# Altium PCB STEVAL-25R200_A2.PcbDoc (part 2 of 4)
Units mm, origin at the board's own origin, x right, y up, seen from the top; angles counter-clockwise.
Board outline 84.5 x 100 mm, 4 copper layers (Top Layer, F2, F3, Bottom Layer), stack 0.78 mm thick; 272 components, 152 nets, 679 pads, 380 vias.
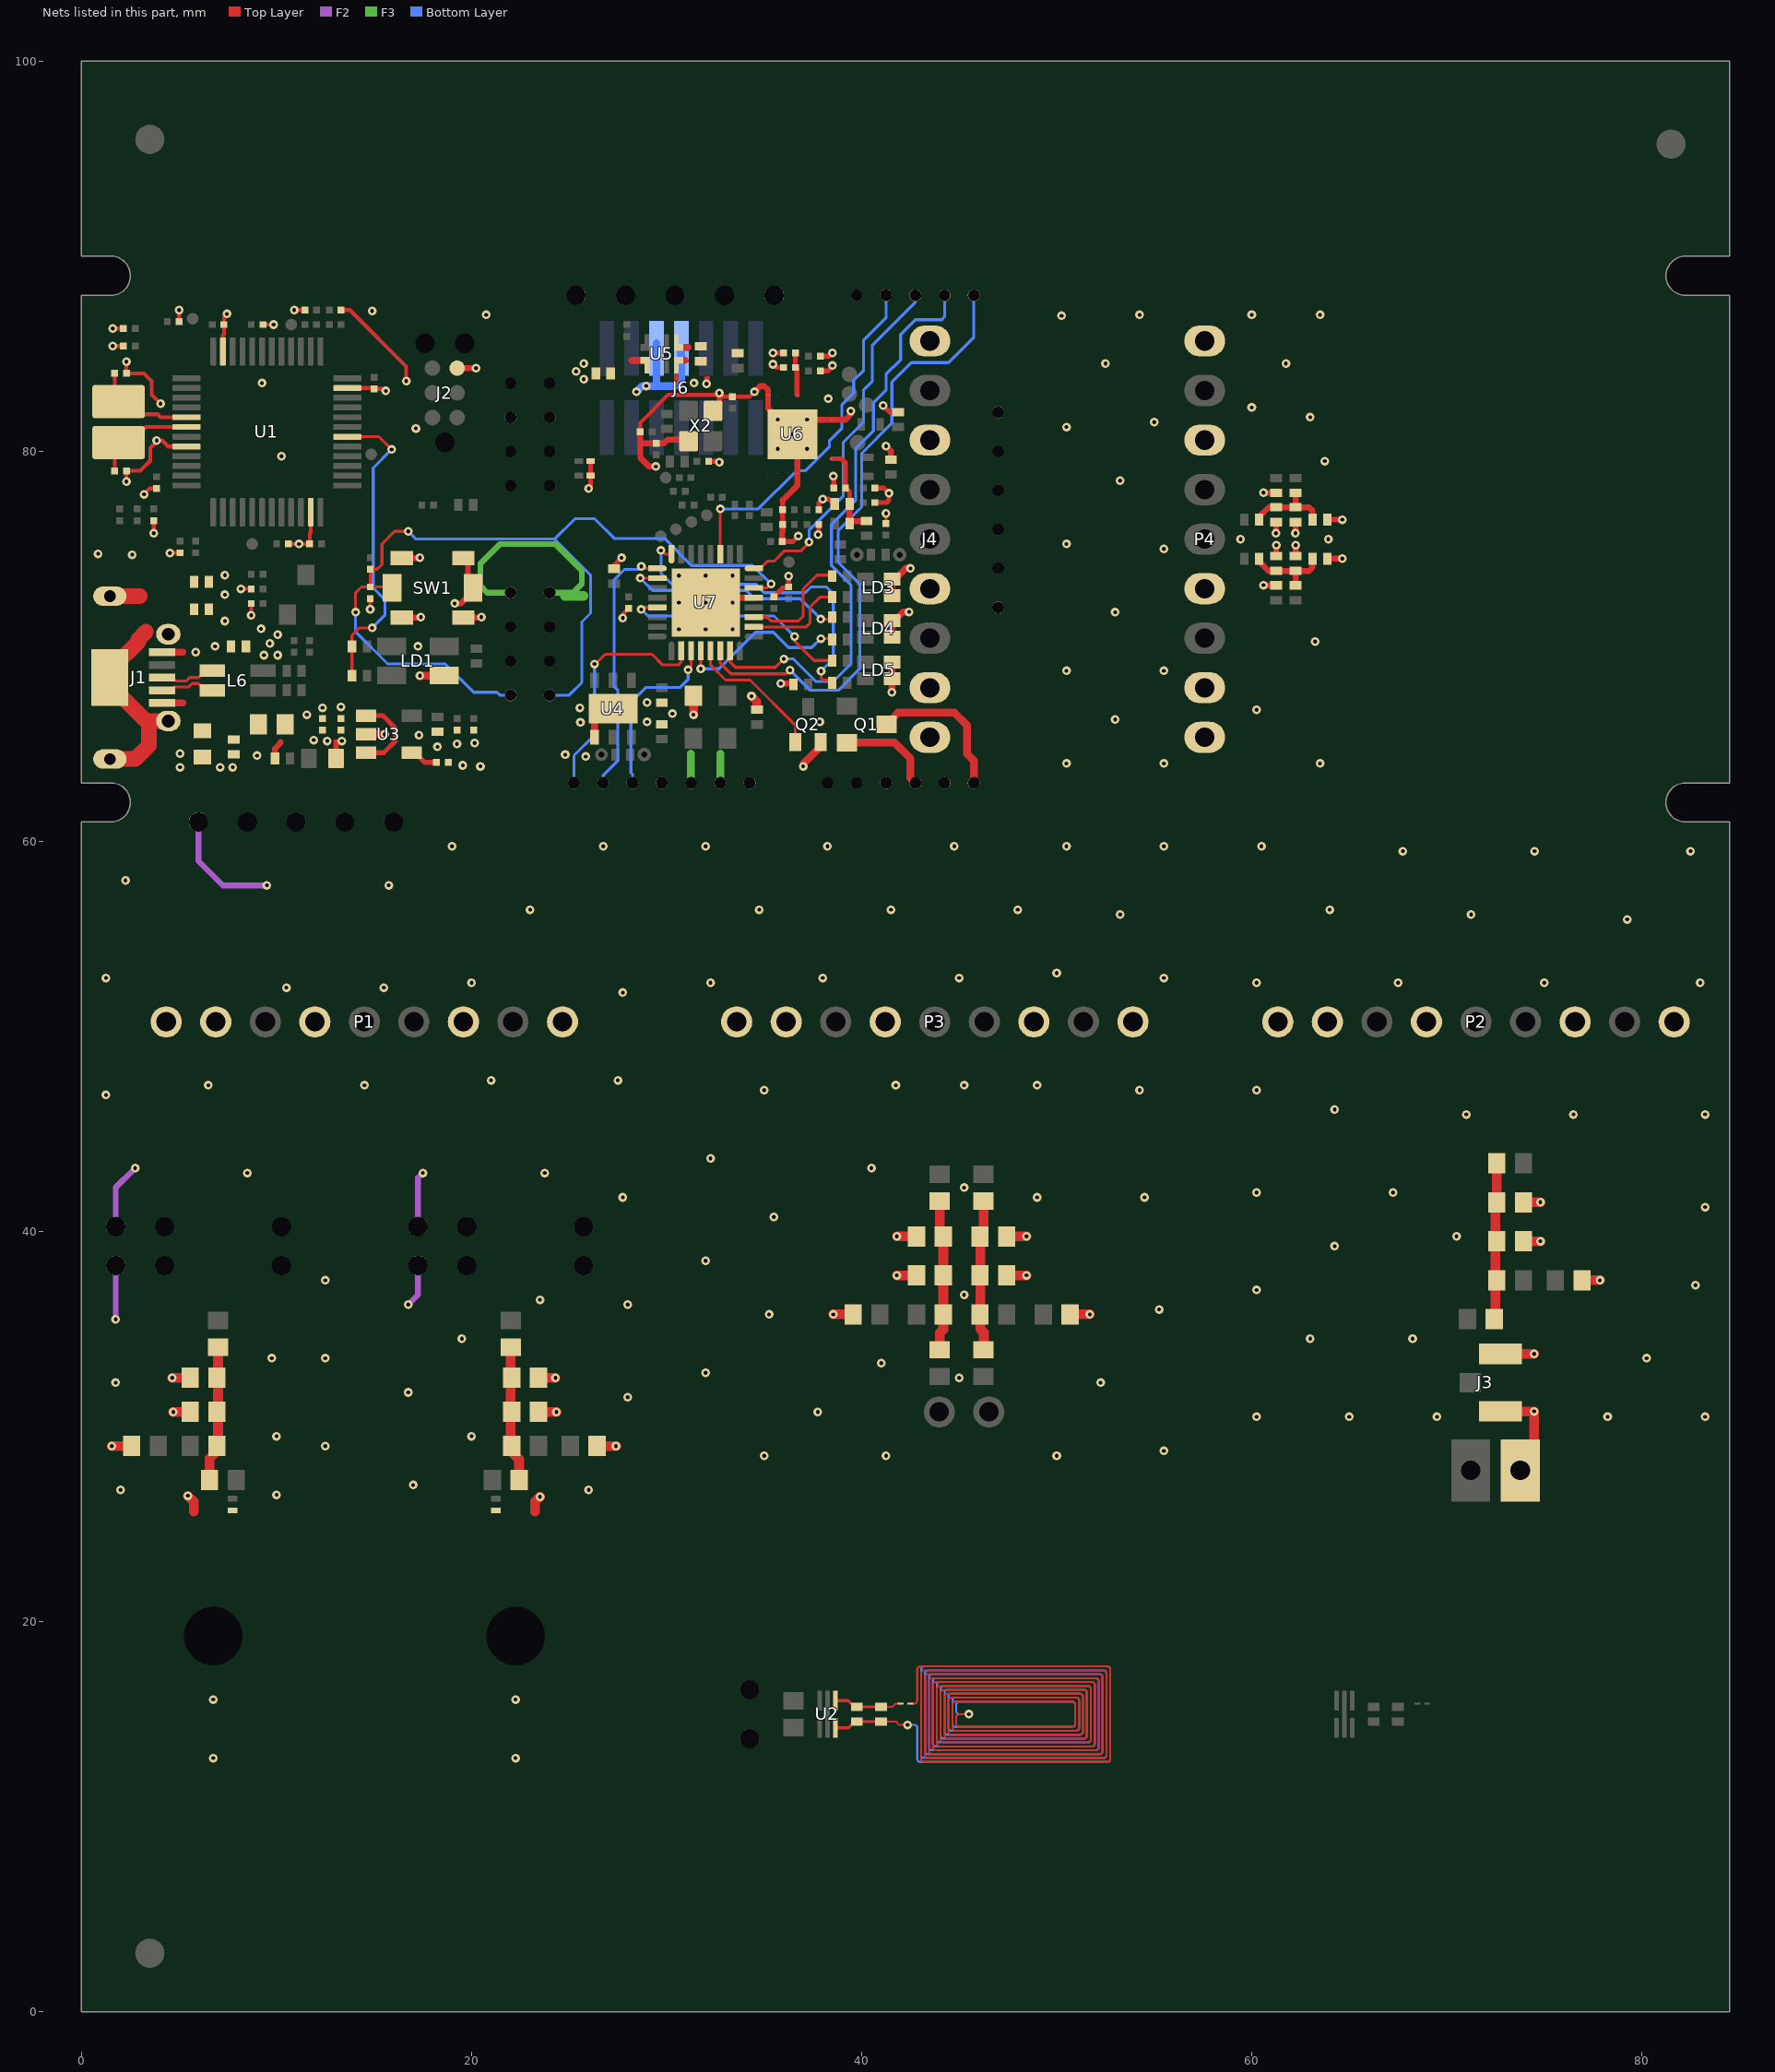
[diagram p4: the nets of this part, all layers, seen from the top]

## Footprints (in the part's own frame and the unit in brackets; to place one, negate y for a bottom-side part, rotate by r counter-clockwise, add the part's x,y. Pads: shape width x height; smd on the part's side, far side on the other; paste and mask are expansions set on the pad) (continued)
ST-QFN24-PAS0.5-4X4-THPAD-2.8MAX [mil]
  round 1 smd: 1(-79.25,49.21) 2(-79.25,29.53) 3(-79.25,9.84) 4(-79.25,-9.84) 5(-79.25,-29.53) 6(-79.25,-49.21) 7(-49.21,-79.25) 8(-29.53,-79.25) 9(-9.84,-79.25) 10(9.84,-79.25) 11(29.53,-79.25) 12(49.21,-79.25) 13(79.25,-49.21) 14(79.25,-29.53) 15(79.25,-9.84) 16(79.25,9.84) 17(79.25,29.53) 18(79.25,49.21) 19(49.21,79.25) 20(29.53,79.25) 21(9.84,79.25) 22(-9.84,79.25) 23(-29.53,79.25) 24(-49.21,79.25)
  rect 100.39x100.39 smd paste-118.11 mask-118.11: 25(0,0)
  Top Layer region: -68.92,43.31 -95.49,43.31 -95.49,55.12 -68.92,55.12 -66.66,54.67 -64.74,53.39 -63.46,51.47 -63.01,49.21 -63.01,49.21 -63.46,46.95 -64.74,45.04 -66.66,43.76 -68.92,43.31
  Top Layer region: -68.92,23.62 -95.49,23.62 -95.49,35.43 -68.92,35.43 -66.66,34.98 -64.74,33.7 -63.46,31.79 -63.01,29.53 -63.01,29.53 -63.46,27.27 -64.74,25.35 -66.66,24.07 -68.92,23.62
  Top Layer region: -68.92,3.94 -95.49,3.94 -95.49,15.75 -68.92,15.75 -66.66,15.3 -64.74,14.02 -63.46,12.1 -63.01,9.84 -63.01,9.84 -63.46,7.58 -64.74,5.67 -66.66,4.39 -68.92,3.94
  Top Layer region: -68.92,-15.75 -95.49,-15.75 -95.49,-3.94 -68.92,-3.94 -66.66,-4.39 -64.74,-5.67 -63.46,-7.58 -63.01,-9.84 -63.01,-9.84 -63.46,-12.1 -64.74,-14.02 -66.66,-15.3 -68.92,-15.75
  Top Layer region: -68.92,-35.43 -95.49,-35.43 -95.49,-23.62 -68.92,-23.62 -66.66,-24.07 -64.74,-25.35 -63.46,-27.27 -63.01,-29.53 -63.01,-29.53 -63.46,-31.79 -64.74,-33.7 -66.66,-34.98 -68.92,-35.43
  Top Layer region: -68.92,-55.12 -95.49,-55.12 -95.49,-43.31 -68.92,-43.31 -66.66,-43.76 -64.74,-45.04 -63.46,-46.95 -63.01,-49.21 -63.01,-49.21 -63.46,-51.47 -64.74,-53.39 -66.66,-54.67 -68.92,-55.12
  Top Layer region: -43.31,-68.92 -43.31,-95.49 -55.12,-95.49 -55.12,-68.92 -54.67,-66.66 -53.39,-64.74 -51.47,-63.46 -49.21,-63.01 -49.21,-63.01 -46.95,-63.46 -45.04,-64.74 -43.76,-66.66 -43.31,-68.92
  Top Layer region: -23.62,-68.92 -23.62,-95.49 -35.43,-95.49 -35.43,-68.92 -34.98,-66.66 -33.7,-64.74 -31.79,-63.46 -29.53,-63.01 -29.53,-63.01 -27.27,-63.46 -25.35,-64.74 -24.07,-66.66 -23.62,-68.92
  Top Layer region: -3.94,-68.92 -3.94,-95.49 -15.75,-95.49 -15.75,-68.92 -15.3,-66.66 -14.02,-64.74 -12.1,-63.46 -9.84,-63.01 -9.84,-63.01 -7.58,-63.46 -5.67,-64.74 -4.39,-66.66 -3.94,-68.92
  Top Layer region: 15.75,-68.92 15.75,-95.49 3.94,-95.49 3.94,-68.92 4.39,-66.66 5.67,-64.74 7.58,-63.46 9.84,-63.01 9.84,-63.01 12.1,-63.46 14.02,-64.74 15.3,-66.66 15.75,-68.92
  Top Layer region: 35.43,-68.92 35.43,-95.49 23.62,-95.49 23.62,-68.92 24.07,-66.66 25.35,-64.74 27.27,-63.46 29.53,-63.01 29.53,-63.01 31.79,-63.46 33.7,-64.74 34.98,-66.66 35.43,-68.92
  Top Layer region: 55.12,-68.92 55.12,-95.49 43.31,-95.49 43.31,-68.92 43.76,-66.66 45.04,-64.74 46.95,-63.46 49.21,-63.01 49.21,-63.01 51.47,-63.46 53.39,-64.74 54.67,-66.66 55.12,-68.92
  Top Layer region: 68.92,-43.31 95.49,-43.31 95.49,-55.12 68.92,-55.12 66.66,-54.67 64.74,-53.39 63.46,-51.47 63.01,-49.21 63.01,-49.21 63.46,-46.95 64.74,-45.04 66.66,-43.76 68.92,-43.31
  Top Layer region: 68.92,-23.62 95.49,-23.62 95.49,-35.43 68.92,-35.43 66.66,-34.98 64.74,-33.7 63.46,-31.79 63.01,-29.53 63.01,-29.53 63.46,-27.27 64.74,-25.35 66.66,-24.07 68.92,-23.62
  Top Layer region: 68.92,-3.94 95.49,-3.94 95.49,-15.75 68.92,-15.75 66.66,-15.3 64.74,-14.02 63.46,-12.1 63.01,-9.84 63.01,-9.84 63.46,-7.58 64.74,-5.67 66.66,-4.39 68.92,-3.94
  Top Layer region: 68.92,15.75 95.49,15.75 95.49,3.94 68.92,3.94 66.66,4.39 64.74,5.67 63.46,7.58 63.01,9.84 63.01,9.84 63.46,12.1 64.74,14.02 66.66,15.3 68.92,15.75
  Top Layer region: 68.92,35.43 95.49,35.43 95.49,23.62 68.92,23.62 66.66,24.07 64.74,25.35 63.46,27.27 63.01,29.53 63.01,29.53 63.46,31.79 64.74,33.7 66.66,34.98 68.92,35.43
  Top Layer region: 68.92,55.12 95.49,55.12 95.49,43.31 68.92,43.31 66.66,43.76 64.74,45.04 63.46,46.95 63.01,49.21 63.01,49.21 63.46,51.47 64.74,53.39 66.66,54.67 68.92,55.12
  Top Layer region: 43.31,68.92 43.31,95.49 55.12,95.49 55.12,68.92 54.67,66.66 53.39,64.74 51.47,63.46 49.21,63.01 49.21,63.01 46.95,63.46 45.04,64.74 43.76,66.66 43.31,68.92
  Top Layer region: 23.62,68.92 23.62,95.49 35.43,95.49 35.43,68.92 34.98,66.66 33.7,64.74 31.79,63.46 29.53,63.01 29.53,63.01 27.27,63.46 25.35,64.74 24.07,66.66 23.62,68.92
  Top Layer region: 3.94,68.92 3.94,95.49 15.75,95.49 15.75,68.92 15.3,66.66 14.02,64.74 12.1,63.46 9.84,63.01 9.84,63.01 7.58,63.46 5.67,64.74 4.39,66.66 3.94,68.92
  Top Layer region: -15.75,68.92 -15.75,95.49 -3.94,95.49 -3.94,68.92 -4.39,66.66 -5.67,64.74 -7.58,63.46 -9.84,63.01 -9.84,63.01 -12.1,63.46 -14.02,64.74 -15.3,66.66 -15.75,68.92
  Top Layer region: -35.43,68.92 -35.43,95.49 -23.62,95.49 -23.62,68.92 -24.07,66.66 -25.35,64.74 -27.27,63.46 -29.53,63.01 -29.53,63.01 -31.79,63.46 -33.7,64.74 -34.98,66.66 -35.43,68.92
  Top Layer region: -55.12,68.92 -55.12,95.49 -43.31,95.49 -43.31,68.92 -43.76,66.66 -45.04,64.74 -46.95,63.46 -49.21,63.01 -49.21,63.01 -51.47,63.46 -53.39,64.74 -54.67,66.66 -55.12,68.92
  silkscreen extent -110,-83 83,83, body extent -83,-83 83,83, height 40
ST-ROHS-CHINOIS-10ans [mm]
  silkscreen extent -3,-2.51 2.99,2.68
ST-ROHS-optimised [mm]
  silkscreen extent -2.76,-1.63 2.72,1.95
ST-ST0201 [mm]
  rect 0.3x0.44 smd: A(0,-0.3) K(0,0.3)
  silkscreen extent -0.57,0.33 -0.43,0.47, body extent -0.18,-0.33 0.18,0.33, height 0.33
ST-UFDFPN5-Pas=0.4-PKG-1.7x1.4 [mm]
  rect 0.25x1 smd: 1(0.4,0.7) 3(-0.4,0.7) 4(-0.4,-0.7) 5(0.4,-0.7)
  rect 0.25x2.4 smd: 2(0,0)
  Top Layer keep-out region: 0.55,0.175 0.15,0.175 0.15,-0.175 0.55,-0.175
  Top Layer keep-out region: -0.55,-0.175 -0.15,-0.175 -0.15,0.175 -0.55,0.175
  silkscreen extent -0.8,-0.75 0.8,1.83, body extent -0.75,-0.9 0.75,0.9, height 0.6
ST-UFQFPN32-PAS-0.5-PKG-5X5X0.55 [mm]
  rect 0.3x0.3 smd: 1(-2.8,1.75) 8(-2.8,-1.75) 9(-1.75,-2.8) 16(1.75,-2.8) 17(2.8,-1.75) 24(2.8,1.75) 25(1.75,2.8) 32(-1.75,2.8)
  oval 0.95x0.3 smd: 1(-2.475,1.75) 8(-2.475,-1.75) 17(2.475,-1.75) 24(2.475,1.75)
  rect 0.95x0.3 smd: 2(-2.475,1.25) 3(-2.475,0.75) 4(-2.475,0.25) 5(-2.475,-0.25) 6(-2.475,-0.75) 7(-2.475,-1.25) 18(2.475,-1.25) 19(2.475,-0.75) 20(2.475,-0.25) 21(2.475,0.25) 22(2.475,0.75) 23(2.475,1.25)
  oval 0.3x0.95 smd: 9(-1.75,-2.475) 16(1.75,-2.475) 25(1.75,2.475) 32(-1.75,2.475)
  rect 0.3x0.95 smd: 10(-1.25,-2.475) 11(-0.75,-2.475) 12(-0.25,-2.475) 13(0.25,-2.475) 14(0.75,-2.475) 15(1.25,-2.475) 26(1.25,2.475) 27(0.75,2.475) 28(0.25,2.475) 29(-0.25,2.475) 30(-0.75,2.475) 31(-1.25,2.475)
  rect 3.5x3.5 smd paste-0.35 mask-0.1: 33(0,0)
  silkscreen extent -3.22,-2.6 2.6,2.72, body extent -2.6,-2.6 2.6,2.6, height 0.61
STRAP-FORMAT-0402-OUVERT [mil]
  rect 24x17 smd paste-39.37: 1(0,-15) 2(0,15)
  Top Layer region: -11.81,20.87 -11.81,1.92 0.05,6.71 11.81,1.96 11.81,20.87
  Top Layer region: -11.81,-22.44 -11.81,-6.97 0,-1.97 11.81,-6.97 11.81,-22.44
  silkscreen extent -22,-2 -22,12, body extent -12,-24 12,24, height 1
STRAP-FORMAT-0603-OUVERT [mil]
  rect 41x35 smd paste-35.43: 1(0,-27) 2(0,27)
  Top Layer region: -20.47,37.4 -20.47,-0.79 0.05,7.5 20.47,-0.75 20.47,37.4
  Top Layer region: -20.47,-38.19 -20.47,-9.84 0,-1.18 20.47,-9.84 20.47,-38.19
  silkscreen extent -31,-37 31,38
TAG-CONNECT-FOOTPRINT-TC2030-IDC-NL [mm]
  round 0.8 smd paste-1: 1(-1.27,-0.635) 2(-1.27,0.635) 3(0,-0.635) 4(0,0.635) 5(1.27,-0.635) 6(1.27,0.635)
  round 0.5 hole 1 unplated: MEC(-2.54,0) MEC(2.54,-1.016) MEC(2.54,1.016)
  Top Layer keep-out region: 0.445,0.635 0.826,0.635 0.826,0.624 0.859,0.458 0.953,0.318 0.953,0.318 1.093,0.224 1.259,0.191 1.259,0.191 1.27,0.191 1.27,-0.19 1.259,-0.19 1.093,-0.224 0.953,-0.318 0.953,-0.317 0.859,-0.458 0.826,-0.624 0.826,-0.624 0.826,-0.635 0.445,-0.635 0.445,-0.624 0.411,-0.458 0.317,-0.318 0.318,-0.318 0.177,-0.224 0.011,-0.191 0.011,-0.191 0,-0.191 0,0.191 0.011,0.191 0.177,0.224 0.317,0.318 0.318,0.318 0.411,0.458 0.445,0.624 0.445,0.624
  Top Layer keep-out region: -0.826,0.635 -0.445,0.635 -0.445,0.624 -0.411,0.458 -0.317,0.318 -0.318,0.318 -0.177,0.224 -0.011,0.191 -0.011,0.191 0,0.191 0,-0.191 -0.011,-0.191 -0.177,-0.224 -0.317,-0.318 -0.318,-0.318 -0.411,-0.458 -0.445,-0.624 -0.445,-0.624 -0.445,-0.635 -0.826,-0.635 -0.826,-0.624 -0.859,-0.458 -0.953,-0.318 -0.953,-0.318 -1.093,-0.224 -1.259,-0.191 -1.259,-0.191 -1.27,-0.191 -1.27,0.19 -1.259,0.19 -1.093,0.224 -0.953,0.318 -0.953,0.317 -0.859,0.458 -0.826,0.624 -0.826,0.624
  silkscreen extent -5,-2.02 4.4,3.1
TAOGLAS-RECE.20279.001E.01 [mm]
  rect 1x1.1 smd: 1(0,-1.55)
  rect 1.05x2.2 smd: 2(-1.475,0) 3(1.475,0)
  silkscreen extent -1.7,-1.4 1.6,1.85, body extent -1.5,-1.55 1.5,1.55, height 1.25
WURTH-WE-CNSW-1206 [mm]
  rect 0.635x1.295 smd: 1(0.5,1.3) 2(0.5,-1.3) 3(-0.5,-1.3) 4(-0.5,1.3)
  silkscreen extent -1.1,-2.22 1.1,2.22, body extent -0.8,-1.6 0.8,1.6, height 1.91

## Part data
ANT1: "ANTENNA FOR HW R+T PROJECT", Manufacturer=N/A
C1: library part "Capacitor 0402 4.7nF 25V 10% X7R", "Capacitor 0402 4.7nF 25V 10% X7R", Manufacturer=MULTI-SOURCES
C2 C3 C4 C5 C6 C7 C10 C15 C18 C41 C42 C43 C51: library part GRM033C71A104KE14D, "Cap GRM033C71A104KE14D 100nF 0201", Manufacturer=MURATA
C8: library part "Capacitor 0402 100pF 50V 5% COG", "Capacitor 0402 100pF 50V 5% COG", Manufacturer=MULTI-SOURCES
C9 C11 C37 C44: library part "Capacitor 0201 10pF 25V", "Capacitor 0201 10pF 25V C0G", Manufacturer=MULTI-SOURCES
C12 C32 C33 C40 C53: library part GRM155R61A475MEAA, "Cap GRM155R61A475MEAA 4.7uF 10V 0402", Manufacturer=MURATA
C13 C27 C28 C67 C76: library part "Capacitor 0603 150pF 50V 2% COG", "Capacitor 0603 150pF 50V 2% COG", Manufacturer=MULTI-SOURCES, Package=0603
C14 C26 C29 C68 C71 C72 C75: library part "Capacitor 0603 10pF 25V 5% C0G", "Capacitor 0603 10pF 25V 5% C0G", Manufacturer=MULTI-SOURCES, Package=0603
C16 C25 C69 C74: library part "Capacitor 0603 39pF 50V 2% COG", "Capacitor 0603 39pF 50V 2% COG", Manufacturer=MULTI-SOURCES, Package=0603
C17 C19 C35 C79: library part GRM033R61A105ME15, "Cap GRM033R61A105ME15 1uF 10V X5R 20% 0201", Manufacturer=MURATA
C20 C36 C38 C45 C47 C49 C52: library part GRM033R61E103KA12D, "Cap GRM033R61E103KA12D 10nF 0201", Manufacturer=MURATA
C21 C24: library part "Capacitor 0603 220pF 50V C0G 2%", "Capacitor 0603 220pF 50V C0G 2%", Manufacturer=MULTI-SOURCES, Package=0603
C22 C23: library part "Capacitor 0603 18pF 50V 2% COG", "Capacitor 0603 18pF 50V 2% COG", Manufacturer=MULTI-SOURCES, Package=0603
C30: library part "Capacitor 0603 240pF 50V 2% COG", "Capacitor 0603 240pF 50V 2% COG", Manufacturer=MULTI-SOURCES, Package=0603
C31: library part "Capacitor 0603 36pF 50V 2% COG", "Capacitor 0603 36pF 50V 2% COG", Manufacturer=MULTI-SOURCES, Package=0603
C34: library part GRM155R61A106ME44D, "Cap GRM155R61A106ME44D 10uF 10V X5R 0402", Manufacturer=MURATA
C39 C46 C48 C50: library part GRM033R61A225ME47, "Capacitor GRM033R61A225ME47 2.2uF 10V 0201", Manufacturer=MURATA
C54 C65: library part "Capacitor 0402 150pF 50V 2% COG", "Capacitor 0402 150pF 50V 2% COG", Manufacturer=MULTI-SOURCES, Package=0402
C55 C64: library part "Capacitor 0402 10pF 25V 5% NPO", "Capacitor 0402 10pF 25V 5% NPO", Manufacturer=MULTI-SOURCES
C56 C63: library part "Capacitor 0402 36pF 50V 2% COG", "Capacitor 0402 36pF 50V 2% COG", Manufacturer=MULTI-SOURCES, Package=0402
C57 C58 C60 C62: library part "Capacitor 0402 240pF 50V 2% COG", "Capacitor 0402 240pF 50V 2% COG", Manufacturer=MULTI-SOURCES, Package=0402
C59 C61: library part "Capacitor 0402 22pF 50V 2% COG", "Capacitor 0402 22pF 50V 2% COG", Manufacturer=MULTI-SOURCES, Package=0402
C66: library part "Capacitor 0603 NC", "Capacitor 0603 NOT FITTED", Manufacturer=MULTI-SOURCES, Package=0603
C70 C73: library part "Capacitor 0603 330pF 25V C0G 2%", "Capacitor 0603 330pF 25V C0G 2%", Manufacturer=MULTI-SOURCES, Package=0603
C77: library part "Capacitor 0402 33pF 50V 5% COG", "Capacitor 0402 33pF 50V 5% COG", Manufacturer=MULTI-SOURCES, Package=0402
C78: library part "Capacitor 0402 6.8pF 50V 5% COG", "Capacitor 0402 6.8pF 50V 5% COG", Manufacturer=MULTI-SOURCES, Package=0402
C80 C81: library part "Capacitor 0201 5.6pF 25V C0G", "Capacitor 0201 5.6pF 25V C0G", Manufacturer=MULTI-SOURCES, Package=0201
D1: "Voltage suppressor ESDA7P60-1U1M", Manufacturer=STMicroelectronics
D2 D3: library part BAT60JFILM-NC, "DIODE BAT60JFILM NOT FITTED", Manufacturer="ST MICRO"
D6 D7: "ESD PROTECT TRANSIL ESDALC6V1-1U2", Manufacturer="ST MICRO"
J1: "47590-0001 - MICRO USB AB", Manufacturer=MOLEX
J2: library part TAG-CONNECT-FOOTPRINT-FOR-TC2030-IDC-NL, "FOOTPRINT FOR TC2030-IDC-NL", Manufacturer="TAG Connect"
J3: "CONN RECE.20279.001E.01", Manufacturer=TAOGLASS
J4: "CONNECTOR TSW-109-08-G-S-NA", Manufacturer=SAMTEC
J6: library part FTSH-107-01-L-DV-K-NC, "CONNECTOR FTSH-107-01-L-DV-K NOT FITTED", Manufacturer=SAMTEC
JP1: library part PADS-x2-CMS-2.0x3.2-PAS-2.54, "2 SMD PADS 2.0x3.2", Manufacturer=N/A
JP2: "CONNECTOR SSW-102-02-G-S-RA", Manufacturer=SAMTEC
L1 L2: library part COILCRAFT-SELF-0402DF-421XJR, "Inductor 0402DF-421XJR 420nH", Manufacturer=COILCRAFT, Package=0402
L3: library part WURTH-742792641, "742792641 EMI FERRITE BEAD 300 Ohms", Manufacturer=WURTH
L4: "SELF BLM15PD121SN1D 0402", Manufacturer=MURATA
L6: library part WURTH-744232090, "744232090 COMMON MODE FILTER", Manufacturer=WURTH
LD1: "LED BICOLOR HSMF-A201-A00J1", Manufacturer=BROADCOM
LD2: library part 19-213SYGC/S530-E2/TR8, "GREEN LED 19-213SYGC/S530-E2/TR8", Manufacturer=EVERLIGHT
LD3 LD4 LD5: "LED BICOLOR LTST-C195KGJRKT", Manufacturer="LITE ON"
MIR1 MIR2 MIR3: library part Mire-Optique, "Fiducial for SMD Components", Manufacturer=N/A
NT_C7_1 NT_C7_2: "Net Tie Width 0.50mm", Manufacturer=N/A
NT_TAG1 NT_TAG2: "Net Tie Width 0.10mm", Manufacturer=N/A
P1 P2 P3 P4: "CONNECTOR SSW-109-02-G-S-RA", Manufacturer=SAMTEC
Q1: "Transistor STR2P3LLH6 SOT23", Manufacturer="ST MICRO"
Q2: "Transistor NHDTC114EU SOT323", Manufacturer=MULTI-SOURCES
Q3: library part MMBT9013L-G-AE3, "Transistor MMBT9013L-G-AE3 NPN", Manufacturer="UNISONIC TECH."
R1 R2: library part "Resistor 0402 10R 1%", "Resistor 0402 10R 1%", Manufacturer=MULTI-SOURCES
R3 R48: library part "Resistor 0201 10K 1%", "Resistor 0201 10K 1%", Manufacturer=MULTI-SOURCES
R4: library part "Resistor 0402 1M 1%", "RESISTOR 0402 1M 1%", Manufacturer=MULTI-SOURCES
R5 R55: library part "Resistor 0201 100R 1%", "Resistor 0201 100R 1%", Manufacturer=MULTI-SOURCES
R6 R15 R39 R47: library part "Resistor 0201 NOT FITTED", "Resistor 0201 NOT FITTED", Manufacturer=MULTI-SOURCES
R7: library part "Resistor 0201 36K 1%", "Resistor 0201 36K 1%", Manufacturer=MULTI-SOURCES
R8: library part "Resistor 0201 1K5 1%", "Resistor 0201 1K5 1%", Manufacturer=MULTI-SOURCES
R9: library part "Resistor 0201 2K7 1%", "RESISTOR 0201 2K7 1%", Manufacturer=MULTI-SOURCES
R10 R38 R41: library part "Resistor 0201 4K7 1%", "RESISTOR 0201 4K7 1%", Manufacturer=MULTI-SOURCES
R11: library part "Resistor 0201 0R NC", "RESISTOR 0201 0R NOT FITTED", Manufacturer=MULTI-SOURCES
R12 R21 R22 R23 R24 R25 R26: library part "Resistor 0402 620R 1%", "RESISTOR 0402 620R 1%", Manufacturer=MULTI-SOURCES
R13 R18 R35 R37 R42 R50 R56 R59: library part "Resistor 0402 0R", "Resistor 0402 0R", Manufacturer=MULTI-SOURCES
R14 R58: library part "Resistor 0402 0R", "Resistor 0402 0R", Manufacturer=MULTI-SOURCES, Package=0402
R16 R17 R19: library part "Resistor 0603 1R5 1%", "RESISTOR 0603 1.5 Ohm 1%", Manufacturer=MULTI-SOURCES, Package=0603
R20: library part "Resistor 0402 10K 1%", "RESISTOR 0402 10K 1%", Manufacturer=MULTI-SOURCES
R27 R28: library part "Resistor 0402 1R13 1%", "RESISTOR 0402 1.13 Ohm 1%", Manufacturer=MULTI-SOURCES, Package=0402
R29 R30 R31 R32 R33 R34 R40 R54: library part "Resistor 0201 0R", "RESISTOR 0201 0R", Manufacturer=MULTI-SOURCES
R36: library part "Resistor 0402 0R NC", "Resistor 0402 0R NOT FITTED", Manufacturer=MULTI-SOURCES
R43 R44: library part "Resistor 0402 100R 1%", "RESISTOR 0402 100R 1%", Manufacturer=MULTI-SOURCES
R45 R46 R49: library part "Resistor 0201 100K 1%", "Resistor 0201 100K 1%", Manufacturer=MULTI-SOURCES
R51 R52: library part "Resistor 0603 560MilliOhm 1%", "Resistor 0603 560MilliOhm 1%", Manufacturer=MULTI-SOURCES, Package=0603
R53 R57: library part "Resistor 0402 TBD", "RESISTOR 0402 TO BE DEFINED (NOT FITTED)", Manufacturer=N/A, Package=0402
SB1: library part STRAP-0603-OUVERT, "SOLDER BRIDGE OPEN SIZE 0603", Manufacturer=N/A, Package=0603
SB2 SB3: library part STRAP-0402-OUVERT, "SOLDER BRIDGE OPEN SIZE 0402", Manufacturer=N/A
SW1: library part PTS820-J20M-SMTR-LFS, "PUSH BUTTON PTS820-J20M-SMTR-LFS", Manufacturer=C&K
TP1 TP2 TP4 TP5: library part PLAGE-CMS-DIAM-0.8mm, "SMD PAD DIAM. 0.8mm", Manufacturer=N/A
TP3 TP6 TP7 TP8 TP14 TP15 TP16 TP17 TP18 TP19: library part PLAGE-CMS-DIAM-0.6mm, "SMD PAD DIAM. 0.6mm", Manufacturer=N/A
U1: "IC STM32F103CBT6 LQFP48", Manufacturer="ST MICRO"
U2: "NFC TAG IC ST25TV02KC-TFH3 UFDFPN5", Manufacturer="ST MICRO"
U3: "LDO LD3985M33R SOT23-5", Manufacturer=STMicroelectronics
U4: "LDO LDO40LPU33RY DFN6", Manufacturer="ST MICRO"
U5: library part ECMF02-4CMX8-NC, "ESD PROTECTION ECMF02-4CMX8 NOT FITTED", Manufacturer="ST MICRO"
U6: "HF READER ST25R200 QFN24", Manufacturer="ST MICRO"
U7: "MCU STM32G0B1KEU6N UFQFPN32", Manufacturer="ST MICRO"
U8: "NFC TAG IC ST25TN01KAFH5 UFDFPN5", Manufacturer="ST MICRO"
V1 V2 V3 V4 V6 V7 V8 V9 V10 V11 V12 V13 V14 V15 V16 V17 V19 V20 V21 V22 V23 V24 V25 V26 V27 V28 V29 V30 V31 V32 V38 V39 V40 V42 V43 V44 V45 V46 V63 V64: library part CASTELLATED_VIA_Drill=0.6-Pad=1.1, "CASTELLATED VIA Drill=0.6 Pad=1.1", Manufacturer=N/A
V5 V18 V33 V34 V35 V36 V37 V41 V47 V48 V49 V50 V51 V52 V53 V54 V55 V56 V57 V58 V59 V60 V61 V62: library part CASTELLATED_VIA, "CASTELLATED_VIA", Manufacturer=N/A
X2: library part NDK-NX2016SA-27.12MHZ-EXS00A-CS01188, "CRYSTAL NX2016SA-27.12MHZ-EXS00A-CS01188 NDK", Manufacturer=NDK
Y1: library part NX3225GD-8MHZ-EXS00A-CG04874, "SMD CRYSTAL NX3225GD-8MHZ-EXS00A-CG04874", Manufacturer=NDK

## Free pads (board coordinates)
  round 0.65 / inner round 0.7 / far side round 0.7 hole 0.3: 1(26.65,64.45)
  round 0.7 hole 0.3: 2(28.85,64.45) 3(39.756,74.7) 4(41.95,74.7)
  round 1 hole 3 unplated: 3(6.75,19.25) 3(22.25,19.25)
  round 2 hole 1: 5(71.23,27.75) 6(73.77,27.75)

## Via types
v1: diameter 0.45, hole 0.2, Top Layer to Bottom Layer, 380 vias

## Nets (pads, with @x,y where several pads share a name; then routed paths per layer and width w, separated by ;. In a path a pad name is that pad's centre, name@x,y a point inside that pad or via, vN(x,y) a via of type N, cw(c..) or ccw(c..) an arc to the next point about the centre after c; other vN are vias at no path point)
5V_USB_CHGR: C17.2 C18.2 D2.A L3.2 R3.2 R9.1 R12.2 R14.1 R20.2 U3.1 U3.3 V1.1 V2.1 V63.1 V64.1 | length 29
  Top Layer w0.19: v1(8.7,71.6) R3.2@8.7,72.2
  Top Layer w0.2: R9.1@13.3,87.25 13.75,87.25 16.65,84.35 v1(16.65,83.6)
  Top Layer w0.25: U3.3@14.58,64.55 15.5,64.55 16.1,65.15 16.1,65.8 15.45,66.45 U3.1@14.58,66.45
  Top Layer w0.3: R12.2@9.919,64.25 9.919,64.769 10.2,65.05 10.2,65.1 ; v1(35.855,68.1) R20.2@36.499,68.1
  Top Layer w0.45: v1(31.375,66.5) D2.A@31.375,67.467 ; v1(34.35,67.45) 34.625,67.175 R14.1@34.625,66.756
  F3 w0.3: V64.1@22,72.75 20.8,72.75 20.45,73.1 20.45,74.25 21.45,75.25 24.3,75.25 25.65,73.9 25.65,73.2 25.2,72.75 V63.1@24,72.75
  F3 w0.4: V1.1@31.25,63 31.25,64.5 ; V2.1@32.75,63 32.75,64.5
  F3 w0.5: 24.78,72.59 25.72,72.59
  other v1: 11.55,66.5 12.35,66.85 13.3,66.9
ADC1_IN1: U7.8 V23.1 | length 18.4
  Top Layer w0.15: U7.8@34.475,74 U7.8@34.8,74 35.17,74.37 35.51,74.37 35.515,74.375 35.516,74.375 36.039,74.897 36.897,74.897 37.35,75.35 v1(37.3,75.35)
  Bottom Layer w0.15: v1(37.3,75.35) 37.3,75.95 39.05,77.7 39.05,80.45 40.09,81.49 40.09,83.14 40.55,83.6 40.55,85.45 42.75,87.65 V23.1@42.75,88
AGD: C35.2 C36.2 U6.15 | length 2.2
  Top Layer w0.25: C35.2@36.6,85.05 C36.2@36.6,84.3 36.675,84.225 36.675,82.913 U6.15@36.7,82.888
AUX_IN: Q1.S V9.1 | length 5
  Top Layer w0.4: Q1.S@39.234,65.06 41.69,65.06 42.5,64.25 42.5,63.25 V9.1@42.75,63
AUX_OUT: Q1.D V10.1 | length 7.8
  Top Layer w0.4: Q1.D@41.266,66 41.866,66.6 44.76,66.6 45.405,65.955 45.405,64.495 45.75,64.15 V10.1@45.75,63
AUX_VCC_EN: Q2.B U7.29 | length 7.2
  Top Layer w0.15: U7.29@32.25,69.775 32.25,69.05 33.027,68.273 34.277,68.273 36.6,65.95 Q2.B@36.6,65.1
D_N: J1.2 L6.4 | length 2.9
  Top Layer w0.15: J1.2@4.125,67.75 4.6,67.75 4.775,67.925 5.499,67.925 5.674,68.1 6,68.1 6.35,67.75 L6.4@6.7,67.75
D_P: J1.3 L6.1 | length 2.9
  Top Layer w0.15: J1.3@4.125,68.4 4.67,68.4 4.845,68.225 5.375,68.225 5.55,68.4 6,68.4 6.35,68.75 L6.1@6.7,68.75
DAC_OUT1: U7.11 V24.1 | length 18.2
  Top Layer w0.15: U7.11@32.75,74.725 v1(32.75,77.05)
  Bottom Layer w0.15: v1(32.75,77.05) 34.7,77.05 36.65,79 37.1,79 38.35,80.25 38.35,80.56 38.99,81.2 38.99,82.39 39.591,82.991 39.591,83.641 40.1,84.15 40.1,85.7 41.25,86.85 41.25,87.3 V24.1@41.25,88
G0_GND_USB: C34.1 R18.2 U5.5 U5.8 V37.1 | length 2.2
  Top Layer w0.25: 30.5,83.65 U5.8@30.5,84.425 ; v1(32.05,83.46) 32.05,83.75 32.1,83.75
  Top Layer w0.35: R18.2@27.131,84.05 R18.2@27.162,84.019 ; 28.225,84.675 U5.5@28.887,84.675 ; U5.8@30.613,84.675 30.95,84.675
  F2 w0.25: v1(32.05,83.46) v1@32.1,83.51
  other v1: 31.4,83.5
G0_VBUS: C34.2 R13.1 U5.1 V33.1 | length 0.5
  Top Layer w0.35: U5.1@30.613,85.325 31.1,85.325
GND: C2.2 C3.2 C4.1 C5.2 C6.2 C7.1 C9.2 C10.2 C11.2 C12.1 C15.1 C17.1 C18.1 C19.1 C20.1 C32.1 C33.1 C35.1 C36.1 C37.1 C38.1 C39.1 C40.1 C41.1 C42.2 C43.1 C44.1 C45.1 C46.1 C47.1 C48.1 C49.1 C50.1 C51.1 C52.1 C53.1 C57.1 C60.2 C79.1 C80.1 C81.2 D6.A D7.A J2.5 J4.1 J4.3 J4.6 J4.8 J4.9 J6.5 J6.7 LD1.K1 LD2.K LD3.K1 LD3.K2 LD4.K1 LD4.K2 LD5.K1 LD5.K2 Q2.E R7.1 R10.2 R18.1 R41.1 R42.2 R46.1 R47.1 R48.1 R49.1 SW1.2 SW1.GND U1.8 U1.23 U1.35 U1.47 U3.2 U4.1 U4.7 U6.4 U6.11 U6.18 U6.25 U7.5 U7.33 V15.1 V16.1 V17.1 V19.1 V20.1 V21.1 V22.1 V45.1 X2.2 X2.4 | length 90.6
  Top Layer w0.2: v1(1.6,85.4) R47.1@2.15,85.4 ; v1(1.6,86.3) R48.1@2.15,86.3 ; v1(2.3,78.45) C11.2@2.3,79 3.011,79 3.525,79.514 3.525,80.175 3.85,80.5 v1(3.85,80.55) 4.15,80.55 4.45,80.25 U1.8@5.375,80.25 ; v1(2.3,84.6) C9.2@2.3,84 3.2,84 3.6,83.6 3.6,82.9 v1(4.05,82.45) ; v1(3.2,77.8) 3.5,78.1 C3.2@3.85,78.1 ; v1(3.7,75.8) R41.1@3.7,76.45 ; v1(4.53,74.79) 4.54,74.79 4.55,74.8 C10.2@5.05,74.8 ; C2.2@5,86.65 v1(5,87.25) ; U1.47@7.25,85.125 7.25,85.95 7.3,86 C5.2@7.3,86.5 7.3,86.9 v1(7.45,87.05) ; v1(8.166,72.95) R7.1@8.7,72.95 ; R46.1@9.3,86.5 v1(9.85,86.5) ; R49.1@10.6,75.25 v1(11.15,75.25) C4.1@11.7,75.25 11.7,75.8 11.75,75.85 U1.23@11.75,76.875 ; v1(10.9,87.25) R10.2@11.45,87.25 ; U1.35@13.625,83.25 14.95,83.25 C6.2@15,83.2 15.5,83.2 v1(15.6,83.1) ; v1(14.8,71.9) C7.1@14.8,72.45 ; v1(27.75,71.45) 27.75,71.65 C42.2@28.05,71.95 ; C80.1@28.65,81.01 28.65,81.47 30.08,82.9 30.6,82.9 ; 30.94,82.9 30.6,82.9 ; v1@32.69,82.8 C37.1@33.375,82.8 33.7,82.8 34.25,82.8 v1(34.5,83.05) ; v1(32.7,82.99) 32.61,82.9 30.6,82.9 ; C79.1@41.25,76.3 v1(41.25,76.82)
  Top Layer w0.25: v1(26,78.1) 26.1,78.2 D6.A@26.1,78.75 D7.A@26.1,79.5 ; C40.1@27.3,73.981 27.3,74.15 v1(27.69,74.54) ; X2.4@30.875,80.275 X2.4@31.125,80.525 X2.4@31.125,80.575 ; C44.1@32.1,79.49 32.7,79.49 v1(32.7,79.44) ; v1(35.447,84.467) 35.614,84.3 C36.1@36,84.3 ; v1(35.45,85.05) C35.1@36,85.05 ; C43.1@35.5,72.55 35.95,73 36.2,73 C41.1@36.25,73.05 v1(36.25,73.6) ; C51.1@35.925,75.375 36.475,75.375 v1(36.75,75.65) ; C50.1@35.95,76.25 C49.1@35.95,77 35.95,77.42 ; v1@37.8,75.7 37.8,75.75 C48.1@37.8,76.25 ; C47.1@37.8,77 37.8,77.35 v1(38,77.55) 38.319,77.55 C53.1@38.619,77.25 ; C38.1@37.875,84.125 38.275,84.125 38.5,84.35 v1(38.5,84.4) ; C39.1@37.875,84.875 38.325,84.875 v1(38.5,85.05) ; v1(38.55,78.725) 38.575,78.75 C52.1@38.575,78.125 ; C46.1@40.675,77.375 41.275,77.375 41.4,77.5 v1(41.4,77.85) 41.125,78.125 C45.1@40.675,78.125 ; v1(41.1,82.35) 41.444,82.006 C57.1@41.875,82.006
  Top Layer w0.3: LD2.K@13.05,64.25 13.05,65.1 ; SW1.GND@16.425,71.475 17.375,71.475 v1(17.4,71.5) ; SW1.GND@16.425,74.525 17.325,74.525 v1(17.35,74.55) ; v1(19.13,72.2) 19.453,72.2 20.075,72.822 SW1.2@20.075,73 19.815,73.26 19.815,74.285 SW1.GND@19.575,74.525 ; J2.5@19.26,84.27 v1(20.23,84.27) ; SW1.GND@19.575,71.475 20.475,71.475 v1(20.5,71.5) ; C80.1@28.65,81.01 28.65,80.407 ; v1(29.45,79.22) 29.1,79.22 28.65,79.67 28.65,80.407 ; X2.4@31.125,80.525 31.042,80.608 30.048,80.608 29.86,80.42 C81.2@29.47,80.42 28.663,80.42 28.65,80.407 ; v1(32,72.25) 32.25,72.5 U7.5@34.475,72.5 ; X2.2@32.375,82.075 32.7,82.4 v1(32.7,82.99) ; v1(34.5,83.05) 34.8,83.35 35,83.35 35.2,83.15 U6.18@35.2,82.888 35.2,82.207 36.45,80.957 v1(36.45,80.875) 36.7,80.625 U6.4@36.7,78.862 36.7,78.25 36.08,77.63 ; C51.1@35.925,75.375 35.925,75.855 35.95,75.88 C50.1@35.95,76.25 ; 35.95,77.42 35.95,77.5 36.08,77.63 ; 36.197,77.747 36.08,77.63 ; v1(37.2,81.625) 38.263,81.625 U6.11@38.463,81.625 39.175,81.625 39.45,81.9 v1(39.45,82.07) ; v1(41.25,80.275) 41.5,80.025 C60.2@41.5,79.631
  Top Layer w0.35: U4.1@26.3,65.162 U4.1@26.3,65.342 26.3,66.415 26.51,66.625 U4.7@27.25,66.625 ; v1(41.55,67.65) LD5.K1@41.55,68.35 LD5.K2@41.55,69.2 ; LD4.K1@41.55,70.475 LD4.K2@41.55,71.325 41.685,71.325 42.13,71.77 v1(42.43,71.77) ; LD3.K1@41.55,72.6 LD3.K2@41.55,73.45 41.723,73.45 42.273,74 v1(42.5,74)
  Top Layer w0.4: U3.2@14.58,65.5 v1(15.55,65.5) ; v1(17.35,68.5) LD1.K1@18.6,68.5 ; v1(37,63.85) 37,63.969 37.9,64.869 Q2.E@37.9,65.1
  Bottom Layer w0.4: v1(28.45,83.05) 28.75,83.35 v1(28.95,83.35) 29.45,83.35 ; J6.5@29.48,85.535 29.48,83.68 29.48,83.38 29.45,83.35 ; J6.7@30.75,85.285 30.75,83.65 30.45,83.35 29.45,83.35
  other v1: 20.45,63.85 19.55,63.9 25.85,64.35 24.8,64.45 18.25,64.85 19.25,65 20.15,65.05 12.6,65.15 13.35,65.15 11.9,65.2 17.3,65.45 25.58,66.1 29,66.125 37.85,66.13 30.3,66.55 25.55,66.85 29,67.125 9.35,69.55 10.05,69.55 17.25,70 9.65,70.15 10.05,70.6 30.625,70.875 32,70.875 33.375,70.875 9.2,70.9 30.625,72.25 33.375,72.25 30.625,73.625 32,73.625 33.375,73.625 2.6,74.7 0.85,74.75 37.77,75.73 10.25,79.75 35.7,80.125 37.2,80.125 17.14,81.18 35.7,81.625 38.29,82.7 9.25,83.5 25.75,83.7 25.35,84.1 25.75,84.5 20.75,87 14.9,87.2
GND_50R: C28.2 C31.1 C66.1 J3.2 J3.3 JP1.1 P2.1 P2.3 P2.6 P2.8 P2.9 pad.6 | length 9.4
  Top Layer w0.5: J3.3@72.75,30.775 v1(74.475,30.775) 74.475,28.455 JP1.1@73.77,27.75 ; J3.2@72.75,33.725 v1(74.475,33.725) ; C66.1@73.936,39.5 v1(74.8,39.5) ; C31.1@73.936,41.5 v1(74.8,41.5) ; C28.2@76.936,37.5 v1(77.85,37.5)
  other v1: 60.25,30.5 65,30.5 69.5,30.5 78.25,30.5 83.25,30.5 80.25,33.5 63,34.5 68.25,34.5 60.25,37 82.75,37.25 64.25,39.25 70.5,39.75 83.25,41.25 60.25,42 67.25,42 71,46 76.5,46 83.25,46 64.25,46.25 60.25,47.25 60.25,52.75 67.5,52.75 75,52.75 83,52.75 79.25,56 71.25,56.25 64,56.5 67.75,59.5 74.5,59.5 82.5,59.5 60.5,59.75
GND_C6_ANT: C54.2 C58.1 C59.1 C61.2 C62.2 C65.1 P4.1 P4.3 P4.6 P4.8 P4.9 | length 3.6
  Top Layer w0.3: v1(60.6,73.142) 60.67,73.142 60.681,73.131 C65.1@61.25,73.131 ; v1(60.6,77.88) 60.67,77.88 60.681,77.869 C54.2@61.25,77.869 ; v1(61.24,75.808) 61.24,75.93 61.25,75.94 C59.1@61.25,76.369 ; C61.2@61.25,74.631 61.25,75.06 61.26,75.07 v1(61.26,75.192) ; v1(62.24,75.808) 62.24,75.93 62.25,75.94 C58.1@62.25,76.369 ; C62.2@62.25,74.631 62.25,75.06 62.26,75.07 v1(62.26,75.192)
  other v1: 50.5,64 55.5,64 63.5,64 53,66.25 60.25,66.75 50.5,68.75 55.5,68.75 63.25,70.25 53,71.75 55.5,75 50.5,75.25 59.43,75.5 63.93,75.5 53.25,78.5 63.75,79.5 50.5,81.25 55,81.5 63,81.75 60,82.25 52.5,84.5 61.75,84.5 50.25,86.95 54.25,87 60,87 63.5,87
GND_FLEX_ANT: C67.2 C70.1 C71.1 C72.2 C73.2 C76.1 P3.1 P3.3 P3.6 P3.8 P3.9 | length 6.1
  Top Layer w0.5: v1(38.55,35.75) C76.1@39.564,35.75 ; v1(41.8,37.75) C72.2@42.814,37.75 ; v1(41.8,39.75) C73.2@42.814,39.75 ; C71.1@47.436,37.75 v1(48.45,37.75) ; C70.1@47.436,39.75 v1(48.45,39.75) ; C67.2@50.686,35.75 v1(51.7,35.75)
  other v1: 35,28.5 41.25,28.5 50,28.5 55.5,28.75 37.75,30.75 52.25,32.25 45,32.5 32,32.75 41,33.25 35.25,35.75 55.25,36 45.25,36.75 32,38.5 35.5,40.75 49,41.75 54.5,41.75 45.25,42.25 40.5,43.25 32.25,43.75 35,47.25 54.25,47.25 41.75,47.5 45.25,47.5 49,47.5 32.25,52.75 38,53 45,53 55.5,53 50,53.25 53.25,56.25 34.75,56.5 41.5,56.5 48,56.5 32,59.75 38.25,59.75 44.75,59.75 50.5,59.75 55.5,59.75
GND_HUB: C13.2 C21.1 C22.1 C23.2 C24.2 C27.1 NT_C7_1.1 NT_C7_2.1 P1.1 P1.3 P1.6 P1.8 P1.9 V48.1 V55.1 V56.1 V57.1 V60.1 | length 24.6
  Top Layer w0.5: v1(1.55,29) C27.1@2.564,29 ; v1(4.65,32.5) C24.2@5.564,32.5 ; v1(4.7,30.75) C23.2@5.564,30.75 ; v1(5.45,26.45) 5.75,26.15 5.75,25.65 ; 23.261,25.64 23.261,26.161 v1(23.5,26.4) ; C21.1@23.436,30.75 v1(24.35,30.75) ; C22.1@23.436,32.5 v1(24.3,32.5) ; C13.2@26.436,29 v1(27.4,29)
  F2 w0.3: v1(1.75,35.5) V55.1@1.75,38.25 ; V48.1@1.75,40.25 1.75,42.25 v1(2.75,43.25) ; V60.1@6,61 6,59 7.25,57.75 v1(9.5,57.75) ; v1(16.75,36.25) 17.25,36.75 V56.1@17.25,38.25 ; V57.1@17.25,40.25 17.25,42.75 v1(17.5,43)
  other v1: 6.75,13 22.25,13 6.75,16 22.25,16 10,26.5 2,26.75 26,26.75 17,27 12.5,29 10,29.5 20,29.5 28,31.5 16.75,31.75 1.75,32.25 9.75,33.5 12.5,33.5 19.5,34.5 28,36.25 23.5,36.5 12.5,37.5 27.75,41.75 8.5,43 23.75,43 1.25,47 6.5,47.5 14.5,47.5 21,47.75 27.5,47.75 27.75,52.25 10.5,52.5 15.5,52.5 20,52.75 1.25,53 23,56.5 15.75,57.75 2.25,58 19,59.75 26.75,59.75
GND_USB: C1.1 C8.1 D1.A J1.5 R4.1 R42.1 | length 1.1
  Top Layer w0.35: J1.5@4.125,69.7 5.2,69.7
  other v1: 5.05,63.8 7.1,63.8 7.75,63.8 9,64.4 5.05,64.5 5.85,69.7 6.85,70 7.35,71.3 7.35,72.65 7.35,73.65
I2C1_SCL: U7.31 V25.1 | length 30.4
  Top Layer w0.15: U7.31@33.25,69.775 33.25,69.2 33.53,68.92 35.57,68.92 v1(36.01,69.36)
  Bottom Layer w0.15: v1(36.01,69.36) 36.49,69.36 37.649,68.201 38.551,68.201 39.45,69.1 39.45,73.15 38.45,74.15 38.45,76.255 39.7,77.505 39.7,80.15 40.6,81.05 40.6,82.49 41.25,83.14 41.25,83.95 42,84.7 42,86 42.75,86.75 44.1,86.75 44.25,86.9 V25.1@44.25,88
I2C1_SDA: U7.30 V26.1 | length 32.6
  Top Layer w0.15: U7.30@32.75,69.775 32.75,69.13 33.29,68.59 36.133,68.59 v1(36.326,68.784)
  Bottom Layer w0.15: v1(36.326,68.784) 37.36,67.75 38.8,67.75 39.9,68.85 39.9,73.2 38.8,74.3 38.8,75.95 40,77.15 40,79.9 41.55,81.45 41.55,83.55 42.55,84.55 44.45,84.55 45.75,85.85 V26.1@45.75,88
I2S2_CK: U7.27 V31.1 | length 9.1
  Top Layer w0.15: v1(31.1,68.8) 31.25,68.95 U7.27@31.25,69.775
  Bottom Layer w0.15: V31.1@28.25,63 28.25,63.45 28.17,63.53 28.17,63.9 28.17,67.12 28.95,67.9 30.7,67.9 31.1,68.3 v1(31.1,68.8)
I2S2_SD: U7.17 V29.1 | length 13.3
  Top Layer w0.15: v1(28.7,74.1) 28.8,74 U7.17@29.2,74 U7.17@29.525,74
  Bottom Layer w0.15: V29.1@26.75,63 26.75,63.4 27.5,64.15 27.5,67.75 27.3,67.95 27.3,73.4 27.85,73.95 28.55,73.95 v1(28.7,74.1)
I2S2_WS: U7.26 V30.1 | length 12.1
  Top Layer w0.15: v1@26.2,69.15 v1@26.225,69.175 ; v1(26.3,69.1) 26.35,69.1 26.85,69.6 29.25,69.6 29.8,69.05 30.416,69.05 30.6,69.05 30.75,69.2 U7.26@30.75,69.775
  Bottom Layer w0.15: V30.1@25.25,63 25.25,64.4 26.3,65.45 v1(26.3,69.1)
LED1_G: R22.2 U7.3 | length 5.9
  Top Layer w0.15: U7.3@34.475,71.5 35.15,71.5 35.35,71.3 36.75,71.3 37,71.55 37,72.95 37.705,73.655 R22.2@38.494,73.655
LED1_R: R21.2 U7.2 | length 5.1
  Top Layer w0.15: U7.2@34.475,71 37.15,71 37.35,71.2 37.35,72.02 37.855,72.525 R21.2@38.494,72.525
LED2_G: R24.2 U7.18 | length 11.6
  Top Layer w0.15: v1(28.65,73.5) U7.18@29.525,73.5 ; v1(37.9,71.4) R24.2@38.494,71.4
  Bottom Layer w0.15: v1(28.65,73.5) 29.275,72.875 34.075,72.875 34.5,72.45 36.85,72.45 v1(37.9,71.4)
LED2_R: R23.2 U7.28 | length 9
  Top Layer w0.15: v1(31.75,68.85) U7.28@31.75,69.775 ; v1(37.903,70.4) 38,70.4 R23.2@38.494,70.4
  Bottom Layer w0.15: v1(31.75,68.85) 32.68,68.85 34.55,70.72 35.47,70.72 36.25,69.94 37.443,69.94 v1(37.903,70.4)
LED3_G: R26.2 U7.21 | length 12
  Top Layer w0.15: v1(28.699,71.896) 28.804,72 U7.21@29.525,72 ; v1@36.59,70.48 v1(36.56,70.51) 36.56,70.27 37.555,69.275 R26.2@38.494,69.275 R26.2@38.494,69.356
  Bottom Layer w0.15: v1(28.699,71.896) 29.035,71.56 35.51,71.56 v1(36.56,70.51)
LED3_R: R25.2 U7.16 | length 16.5
  Top Layer w0.15: v1(29.71,74.92) 29.73,74.92 29.925,74.725 U7.16@30.25,74.725 ; v1(37.92,68.73) 37.92,68.38 38.025,68.275 R25.2@38.494,68.275
  Bottom Layer w0.15: v1(29.71,74.92) 29.71,73.75 30.285,73.175 34.575,73.175 35,72.75 37.1,72.75 37.4,73.05 38.2,73.05 38.55,72.7 38.55,69.36 v1(37.92,68.73)
LED_STLINK: R43.2 R44.2 U1.30 | length 15.9
  Top Layer w0.15: U1.30@13.625,80.75 15.25,80.75 v1(15.9,80.1) ; R43.2@13.869,68.5 R44.2@13.869,70 13.869,70.569 14.25,70.95 v1(14.9,70.95)
  Bottom Layer w0.15: v1(14.9,70.95) 15.55,71.6 15.55,72.4 14.95,73 14.95,79.15 v1(15.9,80.1)
N_RST_G0: C7.2 R54.1 SW1.1 U7.6 V8.1 V40.1 | length 49.4
  Top Layer w0.15: v1(14.05,71.753) 14.05,72.75 14.35,73.05 C7.2@14.8,73.05 ; SW1.1@15.925,73 15.875,73.05 C7.2@14.8,73.05 ; v1(16.75,75.9) 16.05,75.9 15.4,75.25 15.4,74.2 15.15,73.95 R54.1@14.8,73.95 C7.2@14.8,73.05 ; U7.6@34.475,73 35.15,73 v1(35.35,73.2)
  Bottom Layer w0.15: v1(14.05,71.753) 14.05,70.75 15.7,69.1 18.65,69.1 20.1,67.65 21.3,67.65 21.45,67.5 V40.1@22,67.5 ; v1(16.75,75.9) 17.15,75.5 24.25,75.5 ; V8.1@24,67.5 25,67.5 25.652,68.152 25.652,71.252 26.1,71.7 26.1,73.65 24.25,75.5 ; v1(35.35,73.2) 34.4,74.15 31.27,74.15 29.885,75.535 27.315,75.535 26.3,76.55 25.3,76.55 24.25,75.5
NetANT1_1: ANT1.1 R28.2 | length 0.8
  Top Layer w0.3: R28.2@63.881,74.5 v1(64.646,74.5)
NetANT1_2: ANT1.2 R27.2 | length 0.8
  Top Layer w0.3: R27.2@63.881,76.5 v1(64.646,76.5)
NetC1_2: C1.2 J1.G1 J1.G2 J1.G3 J1.G4 J1.G5 R4.2 | length 12
  Top Layer w0.8: J1.G4@1.45,64.225 2.755,64.225 3.45,64.92 3.45,66.172 ; J1.G5@1.45,68.4 J1.G5@1.65,68.4 ; J1.G3@1.45,72.575 2.991,72.575 ; 3.3,70.75 2.9,70.35 2.9,70.226 1.65,68.976 J1.G5@1.65,68.4 ; 3.304,66.17 1.65,67.824 J1.G5@1.65,68.4 ; 3.65,66.175 J1.G2@4.45,66.175
NetC8_2: C8.2 D1.K J1.1 L3.1 | length 1.1
  Top Layer w0.35: J1.1@4.125,67.1 5.2,67.1
NetC9_1: C9.1 U1.5 Y1.2 | length 5.3
  Top Layer w0.2: C9.1@1.7,84 1.7,82.75 Y1.2@1.9,82.55 2.55,81.9 3.9,81.9 4.05,81.75 U1.5@5.375,81.75
NetC11_1: C11.1 U1.6 Y1.1 | length 5.1
  Top Layer w0.2: C11.1@1.7,79 1.7,80.25 Y1.1@1.9,80.45 2.5,80.45 3.3,81.25 U1.6@5.125,81.25
NetC14_1: C14.1 C16.2 C21.2 C22.2 R16.1 | length 7
  Top Layer w0.5: C16.2@22,34.064 22,32.5 22,30.75 22,29 22,28.75 22.436,28.314 R16.1@22.436,27.25
NetC20_2: C20.2 U3.4 | length 1.5
  Top Layer w0.25: U3.4@16.92,64.55 17.1,64.55 17.6,64.05 C20.2@18.2,64.05
NetC23_1: C23.1 C24.1 C25.2 C26.2 R17.1 | length 7
  Top Layer w0.5: R17.1@6.564,27.25 6.564,28.364 7,28.8 7,29 7,30.75 7,32.5 C25.2@7,34.064
NetC29_1: C29.1 C30.2 C31.2 C66.2 R19.1 | length 8.1
  Top Layer w0.5: R19.1@72.436,35.5 72.5,35.564 72.5,37.5 72.5,39.5 72.5,41.64 72.564,41.705 C30.2@72.564,43.5
NetC52_2: C52.2 C53.2 R36.1 R59.1 U6.7 | length 5.2
  Top Layer w0.25: U6.7@38.463,79.625 38.951,79.625 39.175,79.401 C52.2@39.175,78.125 39.381,77.919 C53.2@39.381,77.25 ; R36.1@39.381,76.3 R36.1@39.531,76.45
  Top Layer w0.3: R36.1@39.381,76.25 C53.2@39.381,77.25 ; R36.1@39.381,76.3 39.496,76.415 R59.1@40.234,76.415
NetC55_1: C55.1 C56.2 C58.2 C59.2 R27.1 | length 4.3
  Top Layer w0.3: C56.2@60.381,76.5 60.381,76.641 60.871,77.131 C59.2@61.25,77.131 C58.2@62.25,77.131 ; C55.1@62.25,77.869 C58.2@62.25,77.131 ; R27.1@63.119,76.5 63.119,76.951 62.939,77.131 C58.2@62.25,77.131
NetC61_1: C61.1 C62.1 C63.2 C64.2 R28.1 | length 4.3
  Top Layer w0.3: C63.2@60.381,74.5 60.381,74.359 60.871,73.869 C61.1@61.25,73.869 C62.1@62.25,73.869 ; C64.2@62.25,73.131 C62.1@62.25,73.869 ; R28.1@63.119,74.5 63.119,74.049 62.939,73.869 C62.1@62.25,73.869
NetC68_1: C68.1 C69.2 C70.2 C71.2 R51.1 | length 7.8
  Top Layer w0.5: R51.1@46.264,33.95 46.264,34.814 46.078,35 46.078,35.764 46.078,37.764 46.078,39.764 46.25,39.936 C69.2@46.25,41.564 C69.2@46.264,41.578
NetC72_1: C72.1 C73.1 C74.2 C75.2 R52.1 | length 7.8
  Top Layer w0.5: R52.1@44,33.936 44,34.8 44.186,34.986 C75.2@44.186,35.75 C72.1@44.186,37.75 C73.1@44.186,39.75 44.014,39.922 44.014,41.55 C74.2@44,41.564
NetC77_1: C77.1 NT_TAG1.1 R53.1 U2.4 | length 3.6
  Top Layer w0.1: R53.1@41,15.631 41.581,15.631 41.75,15.8 NT_TAG1.1@42,15.8
  Top Layer w0.15: U2.4@38.65,15.95 39.304,15.95 39.623,15.631 C77.1@39.75,15.631 R53.1@41,15.631
NetC77_2: C77.2 NT_TAG1.2 R53.2 U2.3 | length 443.5
  Top Layer w0.1: R53.2@41,14.869 41.761,14.869 41.93,14.7 v1(42.35,14.7) ; NT_TAG1.2@42.55,15.8 42.7,15.8 ccw(c42.7,15.95) 42.85,15.95 42.85,17.55 cw(c43,17.55) 43,17.7 52.6,17.7 cw(c52.6,17.55) 52.75,17.55 52.75,12.95 cw(c52.6,12.95) 52.6,12.8 43.2,12.8 cw(c43.2,12.95) 43.05,12.95 43.05,17.35 cw(c43.2,17.35) 43.2,17.5 ; 43.2,17.5 52.4,17.5 cw(c52.4,17.35) 52.55,17.35 52.55,13.15 cw(c52.4,13.15) 52.4,13 43.4,13 cw(c43.4,13.15) 43.25,13.15 43.25,17.15 cw(c43.4,17.15) 43.4,17.3 52.2,17.3 cw(c52.2,17.15) 52.35,17.15 52.35,13.35 cw(c52.2,13.35) 52.2,13.2 43.6,13.2 cw(c43.6,13.35) 43.45,13.35 43.45,16.95 cw(c43.6,16.95) 43.6,17.1 52,17.1 cw(c52,16.95) 52.15,16.95 52.15,13.55 cw(c52,13.55) 52,13.4 43.8,13.4 cw(c43.8,13.55) 43.65,13.55 43.65,16.75 cw(c43.8,16.75) 43.8,16.9 51.8,16.9 cw(c51.8,16.75) 51.95,16.75 51.95,13.75 cw(c51.8,13.75) 51.8,13.6 44,13.6 cw(c44,13.75) 43.85,13.75 43.85,16.55 cw(c44,16.55) 44,16.7 51.6,16.7 ; v1(45.5,15.25) 45,15.25 ccw(c45,15.1) 44.85,15.1 44.85,14.75 ccw(c45,14.75) 45,14.6 50.8,14.6 ccw(c50.8,14.75) 50.95,14.75 50.95,15.75 ccw(c50.8,15.75) 50.8,15.9 44.8,15.9 ccw(c44.8,15.75) 44.65,15.75 44.65,14.55 ccw(c44.8,14.55) 44.8,14.4 51,14.4 ccw(c51,14.55) 51.15,14.55 51.15,15.95 ccw(c51,15.95) 51,16.1 44.6,16.1 ccw(c44.6,15.95) 44.45,15.95 44.45,14.35 ccw(c44.6,14.35) 44.6,14.2 51.2,14.2 ccw(c51.2,14.35) 51.35,14.35 51.35,16.15 ccw(c51.2,16.15) 51.2,16.3 44.4,16.3 ccw(c44.4,16.15) 44.25,16.15 44.25,14.15 ccw(c44.4,14.15) 44.4,14 51.4,14 ccw(c51.4,14.15) 51.55,14.15 51.55,16.35 ccw(c51.4,16.35) 51.4,16.5 44.2,16.5 ccw(c44.2,16.35) 44.05,16.35 44.05,13.95 ccw(c44.2,13.95) 44.2,13.8 51.6,13.8 ccw(c51.6,13.95) 51.75,13.95 51.75,16.55 ccw(c51.6,16.55) 51.6,16.7
  Top Layer w0.15: U2.3@38.65,14.55 39.32,14.55 39.639,14.869 C77.2@39.75,14.869 R53.2@41,14.869
  Bottom Layer w0.1: v1(42.35,14.7) 42.7,14.7 cw(c42.7,14.55) 42.85,14.55 42.85,12.95 ccw(c43,12.95) 43,12.8 52.6,12.8 ccw(c52.6,12.95) 52.75,12.95 52.75,17.55 ccw(c52.6,17.55) 52.6,17.7 43.2,17.7 ccw(c43.2,17.55) 43.05,17.55 43.05,13.15 ccw(c43.2,13.15) 43.2,13 52.4,13 ccw(c52.4,13.15) 52.55,13.15 52.55,17.35 ccw(c52.4,17.35) 52.4,17.5 43.4,17.5 ; 43.4,17.5 ccw(c43.4,17.35) 43.25,17.35 43.25,13.35 ccw(c43.4,13.35) 43.4,13.2 52.2,13.2 ccw(c52.2,13.35) 52.35,13.35 52.35,17.15 ccw(c52.2,17.15) 52.2,17.3 43.6,17.3 ccw(c43.6,17.15) 43.45,17.15 43.45,13.55 ccw(c43.6,13.55) 43.6,13.4 52,13.4 ccw(c52,13.55) 52.15,13.55 52.15,16.95 ccw(c52,16.95) 52,17.1 43.8,17.1 ccw(c43.8,16.95) 43.65,16.95 43.65,13.75 ccw(c43.8,13.75) 43.8,13.6 51.8,13.6 ccw(c51.8,13.75) 51.95,13.75 51.95,16.75 ccw(c51.8,16.75) 51.8,16.9 44,16.9 ccw(c44,16.75) 43.85,16.75 43.85,13.95 ccw(c44,13.95) 44,13.8 51.6,13.8 ccw(c51.6,13.95) 51.75,13.95 51.75,16.55 ccw(c51.6,16.55) 51.6,16.7 ; v1(45.5,15.25) 45,15.25 cw(c45,15.4) 44.85,15.4 44.85,15.75 cw(c45,15.75) 45,15.9 50.8,15.9 cw(c50.8,15.75) 50.95,15.75 50.95,14.75 cw(c50.8,14.75) 50.8,14.6 44.8,14.6 cw(c44.8,14.75) 44.65,14.75 44.65,15.95 cw(c44.8,15.95) 44.8,16.1 51,16.1 cw(c51,15.95) 51.15,15.95 51.15,14.55 cw(c51,14.55) 51,14.4 44.6,14.4 cw(c44.6,14.55) 44.45,14.55 44.45,16.15 cw(c44.6,16.15) 44.6,16.3 51.2,16.3 cw(c51.2,16.15) 51.35,16.15 51.35,14.35 cw(c51.2,14.35) 51.2,14.2 44.4,14.2 cw(c44.4,14.35) 44.25,14.35 44.25,16.35 cw(c44.4,16.35) 44.4,16.5 51.4,16.5 cw(c51.4,16.35) 51.55,16.35 51.55,14.15 cw(c51.4,14.15) 51.4,14 44.2,14 cw(c44.2,14.15) 44.05,14.15 44.05,16.55 cw(c44.2,16.55) 44.2,16.7 51.6,16.7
